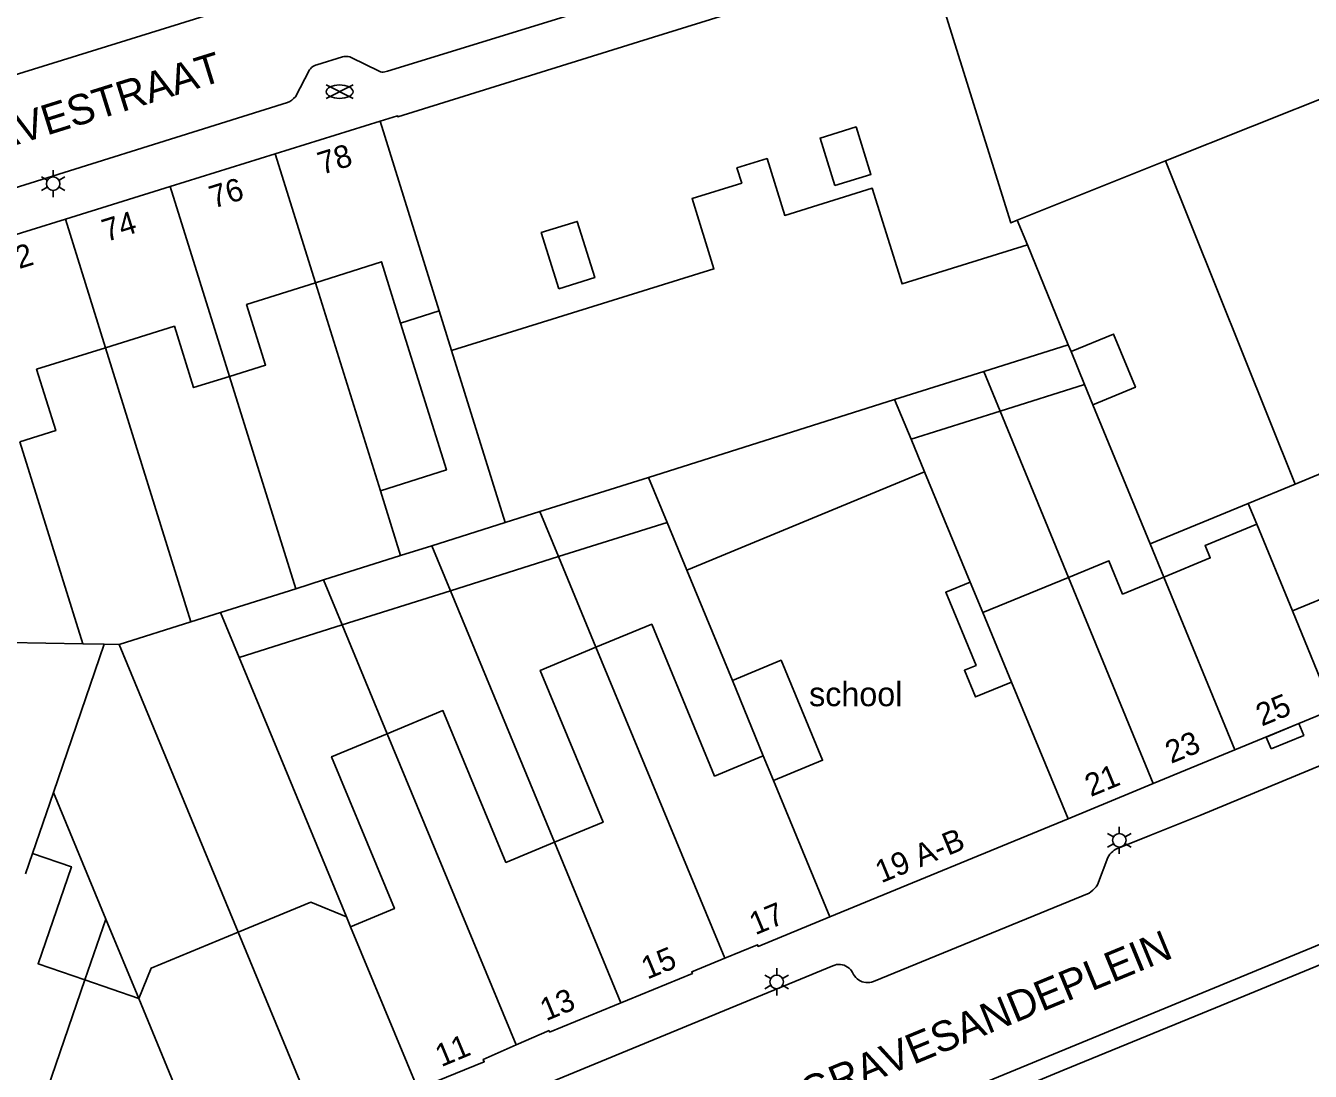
# Model space of a CAD drawing. Extents: x 122462 to 123306, y 485548 to 486417.
# Drawn here: x 122810 to 122895.2, y 485824.2 to 485893.5 of the extents above; entities that cross this region are included whole.
import ezdxf

# ---------------------------------------------------------------- set-up
doc = ezdxf.new("R2010")
doc.units = 0
for name, color, linetype in [('Level 1', 7, 'Continuous'), ('Level 10', 7, 'Continuous'), ('Level 17', 7, 'Continuous'), ('Level 19', 7, 'Continuous'), ('Level 2', 7, 'Continuous'), ('Level 4', 7, 'Continuous'), ('Level 5', 7, 'Continuous'), ('Level 50', 7, 'Continuous'), ('Level 52', 7, 'Continuous'), ('Level 58', 7, 'Continuous'), ('Level 59', 7, 'Continuous'), ('Level 62', 7, 'Continuous')]:
    doc.layers.add(name, color=color, linetype=linetype)

msp = doc.modelspace()

# ---------------------------------------------------------------- linework, layer by layer
at = {"layer": 'Level 1'}
for p, q in [((122826.533, 485884.986), (122833.489, 485887.15)), ((122819.576, 485882.821), (122826.533, 485884.986)), ((122885.562, 485884.524), (122875.729, 485880.584)), ((122894.152, 485863.086), (122885.562, 485884.524)), ((122812.618, 485880.656), (122819.576, 485882.821)), ((122805.66, 485878.489), (122812.618, 485880.656)), ((122875.729, 485880.584), (122876.399, 485878.953)), ((122838.224, 485871.945), (122841.775, 485860.543)), ((122844.075, 485861.27), (122851.274, 485863.544)), ((122851.274, 485863.544), (122852.509, 485860.561)), ((122853.824, 485857.385), (122869.58, 485863.908)), ((122869.58, 485863.908), (122872.605, 485856.601)), ((122895.973, 485863.834), (122894.152, 485863.086)), ((122834.84, 485858.353), (122833.5, 485862.649)), ((122841.775, 485860.543), (122844.075, 485861.27)), ((122852.509, 485860.561), (122845.309, 485858.287)), ((122891.611, 485860.443), (122893.971, 485854.699)), ((122829.739, 485856.742), (122834.84, 485858.353)), ((122845.309, 485858.287), (122838.148, 485856.025)), ((122827.89, 485856.158), (122829.739, 485856.742)), ((122856.849, 485850.078), (122853.824, 485857.385)), ((122873.443, 485854.578), (122879.128, 485856.914)), ((122822.911, 485854.585), (122827.89, 485856.158)), ((122838.148, 485856.025), (122830.973, 485853.759)), ((122893.971, 485854.699), (122897.589, 485856.186)), ((122824.144, 485851.602), (122822.911, 485854.585)), ((122875.349, 485849.974), (122873.443, 485854.578)), ((122830.973, 485853.759), (122824.144, 485851.602)), ((122896.66, 485848.15), (122890.15, 485845.469)), ((122890.15, 485845.469), (122884.745, 485843.241)), ((122858.883, 485845.072), (122859.56, 485843.436)), ((122879.1, 485840.91), (122863.299, 485834.4)), ((122809.978, 485837.258), (122810.439, 485838.605)), ((122831.25, 485834.408), (122831.525, 485833.745)), ((122813.914, 485830.224), (122817.48, 485828.994))]:
    msp.add_line(p, q, dxfattribs=at)
for points in [[(122833.489, 485887.15), (122834.64, 485887.509), (122834.658, 485887.453), (122851.618, 485892.733), (122868.578, 485898.013), (122868.559, 485898.069), (122869.689, 485898.41)], [(122863.634, 485882.883), (122862.653, 485886.034), (122865.04, 485886.777), (122866.021, 485883.626), (122863.634, 485882.883)], [(122876.399, 485878.953), (122868.092, 485876.367), (122866.117, 485882.713), (122860.312, 485880.906), (122859.138, 485884.676), (122857.147, 485884.056), (122857.459, 485883.056), (122854.168, 485882.031), (122855.621, 485877.361), (122838.224, 485871.945)], [(122845.328, 485876.042), (122844.169, 485879.766), (122846.556, 485880.509), (122847.715, 485876.785), (122845.328, 485876.042)], [(122834.842, 485873.775), (122833.575, 485877.837), (122829.195, 485876.45)], [(122829.195, 485876.45), (122824.633, 485875), (122825.887, 485870.982), (122823.5, 485870.237)], [(122833.5, 485862.649), (122837.881, 485864.034), (122834.842, 485873.775)], [(122823.5, 485870.237), (122821.114, 485869.493), (122819.847, 485873.556), (122815.276, 485872.131)], [(122815.276, 485872.131), (122810.708, 485870.706), (122811.975, 485866.643), (122809.588, 485865.899)], [(122885.443, 485856.931), (122888.529, 485858.198), (122888.185, 485859.035), (122891.611, 485860.443)], [(122879.128, 485856.914), (122881.807, 485858.014), (122882.713, 485855.809), (122885.443, 485856.931)], [(122872.605, 485856.601), (122870.988, 485855.931), (122872.999, 485851.075), (122872.227, 485850.755), (122872.96, 485848.985), (122875.349, 485849.974)], [(122847.796, 485852.279), (122851.492, 485853.809), (122855.661, 485843.738), (122858.883, 485845.072)], [(122845.054, 485839.346), (122848.27, 485840.678), (122844.101, 485850.749), (122847.796, 485852.279)], [(122859.56, 485843.436), (122862.818, 485844.785), (122860.074, 485851.413), (122856.849, 485850.078)], [(122833.958, 485846.55), (122837.654, 485848.08), (122841.824, 485838.009), (122845.054, 485839.346)], [(122831.525, 485833.745), (122834.433, 485834.949), (122830.263, 485845.02), (122833.958, 485846.55)], [(122884.745, 485843.241), (122883.423, 485842.695), (122879.1, 485840.91)], [(122810.439, 485838.605), (122813.02, 485837.723), (122810.804, 485831.296), (122813.914, 485830.224)], [(122824.083, 485833.394), (122828.892, 485835.385), (122831.25, 485834.408)], [(122863.299, 485834.4), (122858.549, 485832.449), (122858.511, 485832.551), (122856.331, 485831.661)], [(122817.48, 485828.994), (122818.314, 485831.006), (122824.083, 485833.394)], [(122856.331, 485831.661), (122854.151, 485830.771), (122854.189, 485830.66), (122844.719, 485826.769), (122844.684, 485826.862), (122842.502, 485825.912)], [(122842.502, 485825.912), (122840.32, 485824.959), (122840.389, 485824.795), (122835.976, 485822.993)]]:
    msp.add_lwpolyline(points, dxfattribs=at)
at = {"layer": 'Level 10'}
msp.add_lwpolyline([(122892.557, 485845.548), (122892.235, 485846.329), (122894.399, 485847.22), (122894.721, 485846.437), (122892.557, 485845.548)], dxfattribs=at)
at = {"layer": 'Level 17'}
for points in [[(122850.865, 485895.683), (122833.972, 485890.481), (122833.884, 485890.444), (122833.791, 485890.42), (122833.696, 485890.411), (122833.6, 485890.416), (122833.506, 485890.434), (122833.416, 485890.467), (122831.564, 485891.379), (122831.472, 485891.414), (122831.377, 485891.438), (122831.28, 485891.451), (122831.182, 485891.452), (122831.085, 485891.441), (122830.989, 485891.419), (122829.297, 485890.902), (122829.198, 485890.874), (122829.104, 485890.832), (122829.017, 485890.778), (122828.938, 485890.712), (122828.869, 485890.636), (122828.811, 485890.551), (122827.866, 485888.769), (122827.75, 485888.657), (122827.624, 485888.556), (122827.489, 485888.468), (122827.346, 485888.392), (122805.468, 485881.555)], [(122825.381, 485895.245), (122808.209, 485889.895)], [(122909.585, 485850.138), (122887.829, 485841.134), (122884.523, 485839.804), (122882.271, 485838.897), (122882.159, 485838.828), (122882.055, 485838.748), (122881.958, 485838.658), (122881.871, 485838.56), (122881.793, 485838.454), (122881.726, 485838.341), (122881.043, 485836.531), (122880.954, 485836.4), (122880.853, 485836.279), (122880.741, 485836.168), (122880.618, 485836.068), (122880.487, 485835.98), (122866.195, 485830.115), (122866.073, 485830.076), (122865.947, 485830.052), (122865.819, 485830.043), (122865.691, 485830.049), (122865.565, 485830.071), (122865.442, 485830.107), (122865.324, 485830.157), (122865.213, 485830.222), (122865.11, 485830.299), (122865.018, 485830.387), (122864.936, 485830.486), (122864.867, 485830.594), (122864.814, 485830.709), (122864.748, 485830.817), (122864.669, 485830.916), (122864.578, 485831.004), (122864.477, 485831.08), (122864.367, 485831.143), (122864.25, 485831.192), (122864.128, 485831.227), (122864.003, 485831.246), (122863.877, 485831.249), (122863.751, 485831.237), (122863.627, 485831.209), (122863.508, 485831.166), (122830.218, 485817.444)], [(122855.988, 485814.507), (122856.297, 485814.728), (122856.616, 485814.936), (122856.942, 485815.132), (122857.276, 485815.314), (122878.84, 485824.259), (122888.871, 485828.382), (122910.71, 485837.359), (122915.056, 485839.117)], [(122856.141, 485816.231), (122888.428, 485829.547), (122911.909, 485839.232)]]:
    msp.add_lwpolyline(points, dxfattribs=at)
at = {"layer": 'Level 19'}
for p, q in [((122879.115, 485872.337), (122876.399, 485878.953)), ((122833.5, 485862.649), (122829.195, 485876.45)), ((122820.941, 485853.964), (122815.276, 485872.131)), ((122827.89, 485856.158), (122823.5, 485870.237)), ((122851.274, 485863.544), (122867.596, 485868.699)), ((122879.128, 485856.914), (122874.602, 485867.933)), ((122884.537, 485859.136), (122880.748, 485868.361)), ((122869.58, 485863.908), (122868.687, 485866.065)), ((122809.588, 485865.899), (122813.766, 485852.502)), ((122891.049, 485861.811), (122894.152, 485863.086)), ((122884.537, 485859.136), (122891.049, 485861.811)), ((122891.049, 485861.811), (122891.611, 485860.443)), ((122852.509, 485860.561), (122853.824, 485857.385)), ((122885.443, 485856.931), (122884.537, 485859.136)), ((122847.796, 485852.279), (122845.309, 485858.287)), ((122872.605, 485856.601), (122873.443, 485854.578)), ((122845.054, 485839.346), (122838.148, 485856.025)), ((122820.941, 485853.964), (122822.911, 485854.585)), ((122816.188, 485852.462), (122820.941, 485853.964)), ((122833.958, 485846.55), (122830.973, 485853.759)), ((122813.766, 485852.502), (122808.879, 485852.584)), ((122815.187, 485852.479), (122811.824, 485842.653)), ((122813.766, 485852.502), (122815.187, 485852.479)), ((122815.187, 485852.479), (122816.188, 485852.462)), ((122824.083, 485833.394), (122816.188, 485852.462)), ((122831.25, 485834.408), (122824.144, 485851.602)), ((122856.849, 485850.078), (122858.883, 485845.072)), ((122810.439, 485838.605), (122811.824, 485842.653)), ((122811.824, 485842.653), (122815.302, 485834.253)), ((122815.302, 485834.253), (122813.914, 485830.224)), ((122815.302, 485834.253), (122817.48, 485828.994))]:
    msp.add_line(p, q, dxfattribs=at)
at = {"layer": 'Level 2'}
for p, q in [((122873.519, 485870.57), (122879.115, 485872.337)), ((122879.115, 485872.337), (122879.301, 485871.884)), ((122880.197, 485869.7), (122879.301, 485871.884)), ((122867.596, 485868.699), (122873.519, 485870.57)), ((122874.602, 485867.933), (122873.519, 485870.57)), ((122880.197, 485869.7), (122874.602, 485867.933)), ((122880.748, 485868.361), (122880.197, 485869.7)), ((122868.687, 485866.065), (122867.596, 485868.699)), ((122874.602, 485867.933), (122868.687, 485866.065))]:
    msp.add_line(p, q, dxfattribs=at)
msp.add_lwpolyline([(122879.301, 485871.884), (122882.115, 485873.04), (122883.562, 485869.517), (122880.748, 485868.361)], dxfattribs=at)
at = {"layer": 'Level 4'}
for p, q in [((122897.547, 485889.318), (122885.562, 485884.524)), ((122833.489, 485887.15), (122837.405, 485874.575)), ((122826.533, 485884.986), (122829.195, 485876.45)), ((122823.5, 485870.237), (122819.576, 485882.821)), ((122815.276, 485872.131), (122812.618, 485880.656)), ((122837.405, 485874.575), (122838.224, 485871.945)), ((122845.309, 485858.287), (122844.075, 485861.27)), ((122836.913, 485859.008), (122841.775, 485860.543)), ((122834.84, 485858.353), (122836.913, 485859.008)), ((122838.148, 485856.025), (122836.913, 485859.008)), ((122830.973, 485853.759), (122829.739, 485856.742)), ((122884.745, 485843.241), (122879.128, 485856.914)), ((122890.15, 485845.469), (122885.443, 485856.931)), ((122896.66, 485848.15), (122893.971, 485854.699)), ((122856.331, 485831.661), (122847.796, 485852.279)), ((122879.1, 485840.91), (122875.349, 485849.974)), ((122842.502, 485825.912), (122833.958, 485846.55)), ((122863.299, 485834.4), (122859.56, 485843.436)), ((122831.525, 485833.745), (122835.976, 485822.993)), ((122829.456, 485820.417), (122824.083, 485833.394)), ((122813.914, 485830.224), (122810.87, 485821.388)), ((122822.249, 485817.469), (122817.48, 485828.994))]:
    msp.add_line(p, q, dxfattribs=at)
msp.add_lwpolyline([(122875.729, 485880.584), (122875.296, 485880.41), (122870.27, 485896.552)], dxfattribs=at)
at = {"layer": 'Level 5'}
for p, q in [((122834.842, 485873.775), (122837.405, 485874.575)), ((122845.054, 485839.346), (122849.456, 485828.716))]:
    msp.add_line(p, q, dxfattribs=at)
at = {"layer": 'Level 50'}
for p, q in [((122811.806, 485883.463), (122811.806, 485883.913)), ((122811.416, 485883.238), (122811.026, 485883.463)), ((122812.585, 485883.463), (122812.195, 485883.238)), ((122811.416, 485882.788), (122811.026, 485882.563)), ((122811.806, 485882.113), (122811.806, 485882.563)), ((122812.585, 485882.563), (122812.195, 485882.788)), ((122882.496, 485839.931), (122882.496, 485840.381)), ((122882.106, 485839.706), (122881.716, 485839.931)), ((122883.275, 485839.931), (122882.885, 485839.706)), ((122882.106, 485839.256), (122881.716, 485839.031)), ((122882.496, 485838.581), (122882.496, 485839.031)), ((122883.275, 485839.031), (122882.885, 485839.256)), ((122859.778, 485830.543), (122859.778, 485830.993)), ((122859.388, 485830.318), (122858.998, 485830.543)), ((122860.557, 485830.543), (122860.167, 485830.318)), ((122859.388, 485829.868), (122858.998, 485829.643)), ((122859.778, 485829.193), (122859.778, 485829.643)), ((122860.557, 485829.643), (122860.167, 485829.868))]:
    msp.add_line(p, q, dxfattribs=at)
for centre in [(122811.806, 485883.013), (122882.496, 485839.481), (122859.778, 485830.093)]:
    msp.add_circle(centre, 0.45, dxfattribs=at)
at = {"layer": 'Level 52'}
for p, q in [((122829.908, 485888.669), (122831.689, 485889.559)), ((122829.908, 485889.559), (122831.689, 485888.669))]:
    msp.add_line(p, q, dxfattribs=at)
msp.add_ellipse((122830.798, 485889.112), major_axis=(0.89, 0), ratio=0.5, dxfattribs=at)

# ---------------------------------------------------------------- texts
at = {"layer": 'Level 58'}
for s, rotation, p in [('78', 17.28553, (122829.626, 485883.593)), ('76', 17.28553, (122822.432, 485881.354)), ('74', 17.28553, (122815.325, 485879.143)), ('72', 17.28553, (122808.487, 485877.015)), ('25', 22.38233, (122891.941, 485847.018)), ('23', 22.38233, (122885.929, 485844.543)), ('21', 22.38233, (122880.602, 485842.344)), ('19 A-B', 22.38233, (122866.708, 485836.621)), ('17', 22.62747, (122858.361, 485833.176)), ('15', 22.62747, (122851.2, 485830.236)), ('13', 22.62747, (122844.488, 485827.478)), ('11', 22.62747, (122837.539, 485824.432))]:
    msp.add_text(s, height=1.5, rotation=rotation, dxfattribs=at).set_placement(p)
at = {"layer": 'Level 59'}
for s, rotation, p in [('TWEEDE BOERHAAVESTRAAT', 17.33147, (122785.568, 485878.141)), ("'S-GRAVESANDEPLEIN", 22.41535, (122858.892, 485820.481))]:
    msp.add_text(s, height=2, rotation=rotation, dxfattribs=at).set_placement(p)
at = {"layer": 'Level 62'}
msp.add_text('school', height=1.6, dxfattribs=at).set_placement((122861.928, 485848.372))

doc.saveas('drawing.dxf')
